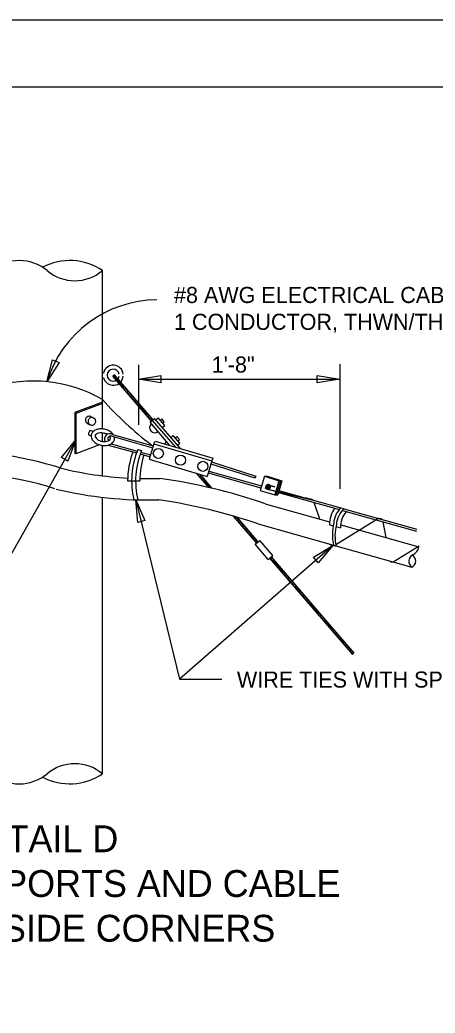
# Model space of a CAD drawing. Extents: x 1299104.8 to 1299141.6, y 239639.8 to 239661.8.
# Drawn here: x 1299131.21 to 1299134.3, y 239654.39 to 239661.79 of the extents above; entities that cross this region are included whole.
import ezdxf

# ---------------------------------------------------------------- set-up
doc = ezdxf.new("R2010")
doc.units = 0
for name, color, linetype in [('DIM TXT', 7, 'Continuous'), ('GS_plotshape_p', 7, 'Continuous'), ('Level 1', 7, 'Continuous')]:
    doc.layers.add(name, color=color, linetype=linetype)

msp = doc.modelspace()

# ---------------------------------------------------------------- linework, layer by layer
at = {"layer": 'DIM TXT'}
for p, q in [((1299131.8243, 239658.7425), (1299131.8243, 239659.9223)), ((1299132.0934, 239659.2193), (1299132.0934, 239658.7737)), ((1299133.5917, 239659.2257), (1299133.5917, 239658.2954)), ((1299131.8243, 239659.1615), (1299131.8325, 239659.1615)), ((1299131.8243, 239659.124), (1299131.8325, 239659.124)), ((1299131.9132, 239659.1462), (1299131.9018, 239659.1364)), ((1299132.1903, 239658.8014), (1299131.9018, 239659.1364)), ((1299131.9132, 239659.1462), (1299131.9116, 239659.125)), ((1299132.2017, 239658.8112), (1299131.9132, 239659.1462)), ((1299131.923, 239659.1348), (1299131.9214, 239659.1136)), ((1299131.9328, 239659.1234), (1299131.9312, 239659.1023)), ((1299131.9425, 239659.1121), (1299131.941, 239659.0909)), ((1299131.9523, 239659.1007), (1299131.9508, 239659.0795)), ((1299131.9621, 239659.0893), (1299131.9605, 239659.0682)), ((1299131.9719, 239659.078), (1299131.9703, 239659.0568)), ((1299131.9817, 239659.0666), (1299131.9801, 239659.0455)), ((1299131.9915, 239659.0552), (1299131.9899, 239659.0341)), ((1299132.0013, 239659.0439), (1299131.9997, 239659.0227)), ((1299132.0934, 239659.1124), (1299133.5917, 239659.1124)), ((1299132.0111, 239659.0325), (1299132.0095, 239659.0114)), ((1299132.0209, 239659.0211), (1299132.0193, 239659)), ((1299132.0307, 239659.0098), (1299132.0291, 239658.9886)), ((1299132.0404, 239658.9984), (1299132.0389, 239658.9773)), ((1299132.0502, 239658.9871), (1299132.0487, 239658.9659)), ((1299132.06, 239658.9757), (1299132.0584, 239658.9545)), ((1299131.8243, 239658.9424), (1299131.6185, 239658.865)), ((1299131.8243, 239658.9331), (1299131.6262, 239658.8586)), ((1299132.0698, 239658.9643), (1299132.0682, 239658.9432)), ((1299132.0796, 239658.953), (1299132.078, 239658.9318)), ((1299132.0894, 239658.9416), (1299132.0878, 239658.9204)), ((1299132.0992, 239658.9302), (1299132.0976, 239658.9091)), ((1299132.109, 239658.9189), (1299132.1074, 239658.8977)), ((1299132.1188, 239658.9075), (1299132.1172, 239658.8863)), ((1299132.1285, 239658.8961), (1299132.127, 239658.875)), ((1299131.6185, 239658.865), (1299131.6185, 239658.5624)), ((1299131.6185, 239658.865), (1299131.6262, 239658.8586)), ((1299131.6262, 239658.8586), (1299131.6262, 239658.5575)), ((1299131.7368, 239658.8352), (1299131.761, 239658.8235)), ((1299132.1383, 239658.8848), (1299132.1368, 239658.8636)), ((1299132.1481, 239658.8734), (1299132.1465, 239658.8522)), ((1299132.1579, 239658.862), (1299132.1563, 239658.8409)), ((1299132.1677, 239658.8507), (1299132.1661, 239658.8295)), ((1299132.1786, 239658.8381), (1299132.177, 239658.8169)), ((1299132.1789, 239658.7917), (1299132.213, 239658.821)), ((1299132.1894, 239658.8254), (1299132.1879, 239658.8043)), ((1299132.4067, 239658.5962), (1299132.213, 239658.821)), ((1299132.2228, 239658.8097), (1299132.2399, 239658.8243)), ((1299132.2888, 239658.7675), (1299132.2399, 239658.8243)), ((1299131.7169, 239658.7813), (1299131.7341, 239658.7728)), ((1299132.3271, 239658.6196), (1299132.1789, 239658.7917)), ((1299132.196, 239658.8063), (1299132.3669, 239658.6079)), ((1299132.2546, 239658.8073), (1299132.2659, 239658.8171)), ((1299132.2855, 239658.7944), (1299132.2659, 239658.8171)), ((1299132.2718, 239658.7528), (1299132.2888, 239658.7675)), ((1299132.2741, 239658.7846), (1299132.2855, 239658.7944)), ((1299131.7196, 239658.6975), (1299131.7401, 239658.6901)), ((1299131.7332, 239658.7325), (1299131.7568, 239658.7239)), ((1299131.8243, 239658.6496), (1299131.8243, 239658.7124)), ((1299131.8863, 239658.6901), (1299132.1991, 239658.6028)), ((1299131.8992, 239658.7021), (1299132.2033, 239658.6172)), ((1299132.3354, 239658.679), (1299132.3525, 239658.6936)), ((1299132.4014, 239658.6368), (1299132.3525, 239658.6936)), ((1299132.3671, 239658.6766), (1299132.3785, 239658.6864)), ((1299132.3981, 239658.6637), (1299132.3785, 239658.6864)), ((1299131.6262, 239658.662), (1299130.2172, 239656.1718)), ((1299131.8028, 239658.6239), (1299131.6262, 239658.5575)), ((1299131.8243, 239658.3931), (1299131.8243, 239658.6193)), ((1299131.8672, 239658.6222), (1299132.0786, 239658.5632)), ((1299131.8899, 239658.6315), (1299132.084, 239658.5773)), ((1299132.2074, 239658.631), (1299132.1735, 239658.5159)), ((1299132.2074, 239658.631), (1299132.2176, 239658.6519)), ((1299132.2074, 239658.631), (1299132.6391, 239658.5039)), ((1299132.2176, 239658.6519), (1299132.6493, 239658.5248)), ((1299132.3844, 239658.6221), (1299132.4014, 239658.6368)), ((1299132.3867, 239658.6539), (1299132.3981, 239658.6637)), ((1299131.6262, 239658.5575), (1299131.6185, 239658.5624)), ((1299132.0886, 239658.5885), (1299132.1153, 239658.5813)), ((1299132.1056, 239658.5556), (1299132.1792, 239658.5351)), ((1299132.1108, 239658.5698), (1299132.1834, 239658.5495)), ((1299132.6391, 239658.5039), (1299132.6493, 239658.5248)), ((1299132.1735, 239658.5159), (1299132.6052, 239658.3888)), ((1299132.6391, 239658.5039), (1299132.6052, 239658.3888)), ((1299132.6318, 239658.4818), (1299132.9593, 239658.3768)), ((1299132.6366, 239658.496), (1299132.9658, 239658.3904)), ((1299132.6175, 239658.3055), (1299132.5256, 239658.4122)), ((1299132.5334, 239658.4099), (1299132.5329, 239658.4037)), ((1299132.5438, 239658.4069), (1299132.5427, 239658.3923)), ((1299132.6423, 239658.2996), (1299132.5521, 239658.4044)), ((1299132.5541, 239658.4021), (1299132.5525, 239658.3809)), ((1299132.5639, 239658.3907), (1299132.5623, 239658.3696)), ((1299132.5737, 239658.3794), (1299132.5721, 239658.3582)), ((1299132.6126, 239658.4141), (1299133.005, 239658.3045)), ((1299132.6169, 239658.4284), (1299133.0092, 239658.3189)), ((1299132.9658, 239658.3904), (1299132.9593, 239658.3768)), ((1299133.0305, 239658.3913), (1299132.9989, 239658.2839)), ((1299133.0305, 239658.3913), (1299133.1384, 239658.3567)), ((1299133.0305, 239658.3913), (1299133.0529, 239658.3909)), ((1299133.0425, 239658.3911), (1299133.1504, 239658.3565)), ((1299133.0529, 239658.3909), (1299133.1608, 239658.3563)), ((1299132.0123, 239658.3564), (1299132.1024, 239658.3564)), ((1299132.5835, 239658.368), (1299132.5819, 239658.3468)), ((1299132.5933, 239658.3566), (1299132.5917, 239658.3355)), ((1299132.603, 239658.3453), (1299132.6015, 239658.3241)), ((1299132.6128, 239658.3339), (1299132.6113, 239658.3127)), ((1299132.6226, 239658.3225), (1299132.6213, 239658.3046)), ((1299132.6324, 239658.3112), (1299132.6317, 239658.3022)), ((1299133.0539, 239658.3102), (1299133.0413, 239658.3055)), ((1299133.0542, 239658.3022), (1299133.0445, 239658.2982)), ((1299133.0502, 239658.3153), (1299133.0533, 239658.317)), ((1299133.0595, 239658.3139), (1299133.0627, 239658.3156)), ((1299133.063, 239658.3051), (1299133.0662, 239658.3067)), ((1299133.0685, 239658.3229), (1299133.1055, 239658.314)), ((1299133.0708, 239658.3204), (1299133.1053, 239658.3121)), ((1299133.1384, 239658.3567), (1299133.1078, 239658.2525)), ((1299133.1504, 239658.3565), (1299133.1194, 239658.2511)), ((1299133.1608, 239658.3563), (1299133.1301, 239658.2521)), ((1299133.1384, 239658.3567), (1299133.1608, 239658.3563)), ((1299131.8243, 239656.1723), (1299131.8243, 239658.2326)), ((1299132.9989, 239658.2839), (1299133.1078, 239658.2525)), ((1299133.0525, 239658.2937), (1299133.3853, 239658.2139)), ((1299133.0571, 239658.2977), (1299133.0603, 239658.2993)), ((1299133.0572, 239658.2945), (1299133.3363, 239658.2275)), ((1299133.1078, 239658.2525), (1299133.1301, 239658.2521)), ((1299133.1252, 239658.2709), (1299133.5892, 239658.1413)), ((1299133.1294, 239658.2853), (1299133.6011, 239658.1536)), ((1299132.0735, 239658.2142), (1299132.3981, 239656.8768)), ((1299133.0362, 239658.185), (1299133.5163, 239658.0502)), ((1299133.3946, 239658.2112), (1299133.3944, 239658.2118)), ((1299133.443, 239658.0707), (1299133.4006, 239658.194)), ((1299133.6027, 239658.1551), (1299133.6248, 239658.1484)), ((1299132.9735, 239657.8922), (1299132.8008, 239658.0927)), ((1299132.8178, 239658.0876), (1299132.8168, 239658.0741)), ((1299132.8282, 239658.0839), (1299132.8266, 239658.0627)), ((1299132.9848, 239657.902), (1299132.8274, 239658.0848)), ((1299133.6113, 239658.1352), (1299134.1641, 239657.9808)), ((1299133.6236, 239658.1473), (1299134.1668, 239657.9956)), ((1299132.838, 239658.0725), (1299132.8364, 239658.0513)), ((1299132.8478, 239658.0611), (1299132.8462, 239658.04)), ((1299132.8576, 239658.0498), (1299132.856, 239658.0286)), ((1299132.8674, 239658.0384), (1299132.8658, 239658.0173)), ((1299132.8771, 239658.027), (1299132.8756, 239658.0059)), ((1299132.8869, 239658.0157), (1299132.8854, 239657.9945)), ((1299132.9842, 239658.0343), (1299133.5457, 239657.8766)), ((1299133.5162, 239658.0287), (1299133.5429, 239658.0213)), ((1299133.5623, 239657.8802), (1299133.8817, 239658.0772)), ((1299133.5635, 239658.0155), (1299133.5985, 239658.0057)), ((1299133.5989, 239658.027), (1299134.1801, 239657.8638)), ((1299133.8817, 239658.0772), (1299133.8988, 239658.0743)), ((1299133.8988, 239658.0743), (1299133.9089, 239658.0686)), ((1299133.9089, 239658.0686), (1299133.9091, 239658.0676)), ((1299133.9122, 239658.0511), (1299133.9345, 239657.9328)), ((1299132.8967, 239658.0043), (1299132.8952, 239657.9832)), ((1299132.9065, 239657.9929), (1299132.9049, 239657.9718)), ((1299132.9163, 239657.9816), (1299132.9147, 239657.9604)), ((1299132.9261, 239657.9702), (1299132.9245, 239657.9491)), ((1299132.9359, 239657.9589), (1299132.9343, 239657.9377)), ((1299132.9457, 239657.9475), (1299132.9441, 239657.9263)), ((1299132.9555, 239657.9361), (1299132.9539, 239657.915)), ((1299133.5403, 239657.8742), (1299132.3981, 239656.8768)), ((1299132.9621, 239657.8824), (1299132.9962, 239657.9118)), ((1299133.06, 239657.7688), (1299132.9621, 239657.8824)), ((1299132.9653, 239657.9248), (1299132.9637, 239657.9036)), ((1299132.975, 239657.9134), (1299132.9735, 239657.8922)), ((1299133.0941, 239657.7982), (1299132.9962, 239657.9118)), ((1299133.5059, 239657.8878), (1299133.5326, 239657.8748)), ((1299133.5326, 239657.8748), (1299133.5512, 239657.8734)), ((1299133.5461, 239657.8749), (1299133.5645, 239657.869)), ((1299133.564, 239657.8715), (1299134.1281, 239657.7131)), ((1299133.99, 239657.7508), (1299134.1826, 239657.8706)), ((1299133.06, 239657.7688), (1299133.0941, 239657.7982)), ((1299133.0827, 239657.7884), (1299133.0812, 239657.7672)), ((1299133.6998, 239657.072), (1299133.0827, 239657.7884)), ((1299133.6894, 239657.0611), (1299133.0714, 239657.7786)), ((1299133.0925, 239657.777), (1299133.0909, 239657.7559)), ((1299133.1023, 239657.7656), (1299133.1007, 239657.7445)), ((1299133.1121, 239657.7543), (1299133.1105, 239657.7331)), ((1299133.1219, 239657.7429), (1299133.1203, 239657.7218)), ((1299133.1317, 239657.7316), (1299133.1301, 239657.7104)), ((1299133.1415, 239657.7202), (1299133.1399, 239657.699)), ((1299133.9673, 239657.7583), (1299133.9674, 239657.758)), ((1299133.9674, 239657.758), (1299133.9757, 239657.7523)), ((1299133.9757, 239657.7523), (1299133.99, 239657.7508)), ((1299133.1513, 239657.7088), (1299133.1497, 239657.6877)), ((1299133.161, 239657.6975), (1299133.1595, 239657.6763)), ((1299133.1708, 239657.6861), (1299133.1693, 239657.6649)), ((1299133.1806, 239657.6747), (1299133.179, 239657.6536)), ((1299133.1904, 239657.6634), (1299133.1888, 239657.6422)), ((1299133.2002, 239657.652), (1299133.1986, 239657.6308)), ((1299133.21, 239657.6406), (1299133.2084, 239657.6195)), ((1299133.2198, 239657.6293), (1299133.2182, 239657.6081)), ((1299133.2296, 239657.6179), (1299133.228, 239657.5967)), ((1299133.2394, 239657.6065), (1299133.2378, 239657.5854)), ((1299133.2492, 239657.5952), (1299133.2476, 239657.574)), ((1299133.2632, 239657.5792), (1299133.2617, 239657.558)), ((1299133.273, 239657.5678), (1299133.2715, 239657.5467)), ((1299133.2828, 239657.5565), (1299133.2812, 239657.5353)), ((1299133.2926, 239657.5451), (1299133.291, 239657.5239)), ((1299133.3024, 239657.5337), (1299133.3008, 239657.5126)), ((1299133.3122, 239657.5224), (1299133.3106, 239657.5012)), ((1299133.322, 239657.511), (1299133.3204, 239657.4898)), ((1299133.3318, 239657.4996), (1299133.3302, 239657.4785)), ((1299133.3416, 239657.4883), (1299133.34, 239657.4671)), ((1299133.3513, 239657.4769), (1299133.3498, 239657.4557)), ((1299133.3611, 239657.4655), (1299133.3596, 239657.4444)), ((1299133.3709, 239657.4542), (1299133.3693, 239657.433)), ((1299133.3803, 239657.4429), (1299133.3787, 239657.4218)), ((1299133.3901, 239657.4316), (1299133.3885, 239657.4104)), ((1299133.3999, 239657.4202), (1299133.3983, 239657.3991)), ((1299133.4096, 239657.4088), (1299133.4081, 239657.3877)), ((1299133.4194, 239657.3975), (1299133.4179, 239657.3763)), ((1299133.4292, 239657.3861), (1299133.4276, 239657.365)), ((1299133.439, 239657.3748), (1299133.4374, 239657.3536)), ((1299133.4488, 239657.3634), (1299133.4472, 239657.3422)), ((1299133.4586, 239657.352), (1299133.457, 239657.3309)), ((1299133.4684, 239657.3407), (1299133.4668, 239657.3195)), ((1299133.4782, 239657.3293), (1299133.4766, 239657.3081)), ((1299133.488, 239657.3179), (1299133.4864, 239657.2968)), ((1299133.4967, 239657.3053), (1299133.4951, 239657.2841)), ((1299133.5064, 239657.2939), (1299133.5049, 239657.2728)), ((1299133.5162, 239657.2825), (1299133.5147, 239657.2614)), ((1299133.526, 239657.2712), (1299133.5245, 239657.25)), ((1299133.5358, 239657.2598), (1299133.5342, 239657.2387)), ((1299133.5456, 239657.2485), (1299133.544, 239657.2273)), ((1299133.5554, 239657.2371), (1299133.5538, 239657.2159)), ((1299133.5652, 239657.2257), (1299133.5636, 239657.2046)), ((1299133.575, 239657.2144), (1299133.5734, 239657.1932)), ((1299133.5848, 239657.203), (1299133.5832, 239657.1818)), ((1299133.5946, 239657.1916), (1299133.593, 239657.1705)), ((1299133.6032, 239657.1819), (1299133.6017, 239657.1607)), ((1299133.6131, 239657.1723), (1299133.6116, 239657.1512)), ((1299133.6225, 239657.1622), (1299133.6209, 239657.1411)), ((1299133.6323, 239657.1508), (1299133.6307, 239657.1297)), ((1299133.6421, 239657.1395), (1299133.6405, 239657.1183)), ((1299133.6519, 239657.1281), (1299133.6503, 239657.107)), ((1299133.6617, 239657.1168), (1299133.6601, 239657.0956)), ((1299133.6715, 239657.1054), (1299133.6699, 239657.0842)), ((1299133.6812, 239657.094), (1299133.6797, 239657.0729)), ((1299133.691, 239657.0827), (1299133.6895, 239657.0615)), ((1299132.3981, 239656.8768), (1299132.7138, 239656.8768))]:
    msp.add_line(p, q, dxfattribs=at)
for points in [[(1299131.4519, 239659.2579), (1299131.5018, 239659.2364), (1299131.411, 239659.0939)], [(1299132.2603, 239659.1396), (1299132.2603, 239659.0852), (1299132.0934, 239659.1124)], [(1299133.4248, 239659.0852), (1299133.4248, 239659.1396), (1299133.5917, 239659.1124)], [(1299131.5677, 239658.5034), (1299131.5204, 239658.5302), (1299131.6262, 239658.662)], [(1299132.141, 239658.0592), (1299132.0884, 239658.0458), (1299132.0735, 239658.2142)], [(1299133.4313, 239657.745), (1299133.3959, 239657.7863), (1299133.5403, 239657.8742)]]:
    msp.add_lwpolyline(points, close=True, dxfattribs=at)
for points in [[(1299133.0502, 239658.3153), (1299133.0443, 239658.3079), (1299133.0447, 239658.3068)], [(1299133.0476, 239658.2995), (1299133.0477, 239658.2991), (1299133.0571, 239658.2977), (1299133.063, 239658.3051)], [(1299133.063, 239658.3051), (1299133.0595, 239658.3139), (1299133.0502, 239658.3153)], [(1299133.0662, 239658.3067), (1299133.0627, 239658.3156), (1299133.0533, 239658.317)], [(1299133.0603, 239658.2993), (1299133.0662, 239658.3067)]]:
    msp.add_lwpolyline(points, dxfattribs=at)
for centre, radius in [((1299132.2407, 239658.5601), 0.0375), ((1299132.4063, 239658.51), 0.0375), ((1299132.5732, 239658.4636), 0.0375), ((1299133.042, 239658.3015), 0.00408)]:
    msp.add_circle(centre, radius, dxfattribs=at)
for centre, radius, start, end in [((1299131.2055, 239659.6762), 0.3211, 50.03379, 129.96621), ((1299131.5805, 239659.5637), 0.4336, 55.79454, 117.85169), ((1299131.618, 239660.1684), 0.3211, 230.03379, 309.96621), ((1299132.239, 239658.8385), 0.8666, 90.62427, 162.85937), ((1299131.9051, 239659.1428), 0.075, 5.73917, 165.52249), ((1299131.9051, 239659.1428), 0.075, 194.47751, 354.26083), ((1299131.9051, 239659.1428), 0.045, 9.59407, 350.40593), ((1299131.3088, 239658.0608), 1.0381, 60.22849, 107.47221), ((1299133.7639, 239660.6889), 2.5971, 221.68102, 232.67437), ((1299131.7267, 239658.8083), 0.0289, 149.78698, 172.19682), ((1299131.7267, 239658.8083), 0.0289, 127.37714, 149.78698), ((1299131.7267, 239658.8084), 0.0287, 104.91468, 127.37714), ((1299131.7266, 239658.8085), 0.0286, 82.37742, 104.91468), ((1299131.7461, 239658.7989), 0.0289, 127.37714, 149.78698), ((1299131.746, 239658.799), 0.0287, 104.91468, 127.37714), ((1299131.7266, 239658.8086), 0.0285, 69.046, 82.37742), ((1299131.746, 239658.7991), 0.0286, 82.37742, 104.91468), ((1299131.746, 239658.7992), 0.0285, 59.78698, 82.37742), ((1299131.746, 239658.7992), 0.0285, 37.19653, 59.78698), ((1299131.7266, 239658.8083), 0.0287, 172.19682, 194.65927), ((1299131.7265, 239658.8082), 0.0286, 194.65927, 217.19653), ((1299131.7264, 239658.8082), 0.0285, 217.19653, 239.78698), ((1299131.7264, 239658.8082), 0.0285, 239.78698, 250.59071), ((1299131.746, 239658.7989), 0.0287, 172.19682, 194.65927), ((1299131.7461, 239658.7989), 0.0289, 149.78698, 172.19682), ((1299131.7459, 239658.7989), 0.0286, 194.65927, 217.19653), ((1299131.7458, 239658.7988), 0.0285, 217.19653, 239.78698), ((1299131.7458, 239658.7988), 0.0285, 239.78698, 262.37742), ((1299131.7458, 239658.7989), 0.0286, 262.37742, 284.91468), ((1299131.7458, 239658.799), 0.0287, 284.91468, 307.37714), ((1299131.7457, 239658.7991), 0.0289, 307.37714, 329.78698), ((1299131.7459, 239658.7992), 0.0286, 14.65927, 37.19653), ((1299131.7457, 239658.7991), 0.0289, 329.78698, 352.19682), ((1299131.7458, 239658.7991), 0.0287, 352.19682, 14.65927), ((1299132.2132, 239658.7519), 0.0375, 130.74057, 310.74057), ((1299131.7728, 239658.697), 0.0532, 167.42818, 179.43021), ((1299131.7728, 239658.697), 0.0532, 138.67908, 167.42818), ((1299131.7889, 239658.6828), 0.0746, 138.29739, 138.67908), ((1299131.7831, 239658.6895), 0.0431, 168.52616, 199.38211), ((1299131.7831, 239658.6895), 0.0431, 137.67021, 168.52616), ((1299131.8068, 239658.6979), 0.0682, 199.38211, 223.79222), ((1299131.8017, 239658.6726), 0.0682, 113.2601, 137.67021), ((1299131.7831, 239658.6895), 0.0131, 168.52616, 199.38211), ((1299131.7831, 239658.6895), 0.0131, 137.67021, 168.52616), ((1299131.8068, 239658.6979), 0.0382, 199.38211, 223.79222), ((1299131.8017, 239658.6726), 0.0382, 113.2601, 137.67021), ((1299131.8115, 239658.6498), 0.093, 94.54907, 113.2601), ((1299131.8115, 239658.6498), 0.063, 94.54907, 113.2601), ((1299131.8142, 239658.6164), 0.1265, 78.52616, 94.54907), ((1299131.8142, 239658.6164), 0.0965, 78.52616, 94.54907), ((1299131.8142, 239658.6164), 0.0965, 62.50325, 78.52616), ((1299131.8142, 239658.6164), 0.1265, 62.50325, 78.52616), ((1299131.88, 239658.6661), 0.0408, 61.92341, 205.91256), ((1299131.8296, 239658.6461), 0.063, 61.46787, 62.50325), ((1299131.8854, 239658.6696), 0.0206, 61.46209, 225.1877), ((1299131.8296, 239658.6461), 0.093, 43.79222, 62.50325), ((1299131.8476, 239658.6633), 0.0382, 19.38211, 40.60323), ((1299131.8713, 239658.6716), 0.0131, 348.52616, 19.38211), ((1299131.8476, 239658.6633), 0.0682, 33.14833, 43.79222), ((1299131.8713, 239658.6716), 0.0431, 348.52616, 14.90203), ((1299131.8248, 239658.715), 0.093, 223.79222, 242.50325), ((1299131.8248, 239658.715), 0.063, 223.79222, 242.50325), ((1299131.8402, 239658.7448), 0.1265, 242.50325, 258.52616), ((1299131.8402, 239658.7448), 0.0965, 242.50325, 258.52616), ((1299131.8402, 239658.7448), 0.1265, 258.52616, 274.54907), ((1299131.8402, 239658.7448), 0.0965, 258.52616, 274.54907), ((1299131.8429, 239658.7113), 0.063, 274.54907, 293.2601), ((1299131.8429, 239658.7113), 0.093, 274.54907, 293.2601), ((1299131.8527, 239658.6886), 0.0382, 293.2601, 317.67021), ((1299131.8527, 239658.6886), 0.0682, 293.2601, 317.67021), ((1299131.8713, 239658.6716), 0.0131, 317.67021, 348.52616), ((1299131.8713, 239658.6716), 0.0431, 317.67021, 348.52616), ((1299132.3258, 239658.6212), 0.0375, 130.74057, 165.28012), ((1299130.7213, 239655.96), 2.6133, 72.24591, 93.70981), ((1299132.6141, 239658.3564), 0.6018, 159.40629, 180), ((1299132.6438, 239658.3564), 0.6018, 157.30675, 193.6218), ((1299132.6734, 239658.3564), 0.6018, 158.04982, 193.71187), ((1299132.7042, 239658.3564), 0.6018, 161.45038, 180), ((1299130.7213, 239655.96), 2.4539, 72.24591, 95.77175), ((1299132.1634, 239661.1268), 2.7546, 256.45152, 266.86214), ((1299132.1634, 239661.1268), 2.7546, 268.73537, 271.85609), ((1299131.6622, 239654.2), 4.2152, 70.97653, 81.9475), ((1299133.057, 239658.3101), 0.0172, 223.69363, 196.41961), ((1299133.043, 239658.3018), 0.00408, 309.40767, 102.03168), ((1299133.044, 239658.3022), 0.00408, 311.84408, 117.1852), ((1299133.0452, 239658.3027), 0.00408, 309.40767, 96.9335), ((1299133.0463, 239658.3031), 0.00408, 311.84408, 98.37244), ((1299133.0474, 239658.3036), 0.00408, 311.84408, 96.13701), ((1299133.0486, 239658.3041), 0.00408, 309.40767, 91.60657), ((1299133.0497, 239658.3045), 0.00408, 311.84408, 92.62242), ((1299133.0597, 239658.3115), 0.0172, 36.4414, 122.35212), ((1299133.0508, 239658.3049), 0.00408, 311.84408, 91.16995), ((1299133.052, 239658.3055), 0.00408, 309.40767, 87.571), ((1299133.053, 239658.3058), 0.00408, 322.72939, 88.40842), ((1299133.0533, 239658.3062), 0.00408, 283.85937, 81.73019), ((1299133.0597, 239658.3115), 0.0172, 292.43109, 27.51642), ((1299132.1634, 239661.1268), 2.914, 256.45152, 271.57798), ((1299131.6622, 239654.2), 4.0558, 70.97653, 81.75694), ((1299131.2816, 239648.3998), 10.0402, 77.98839, 78.19132), ((1299133.353, 239658.1351), 0.087, 61.16103, 77.98839), ((1299133.7181, 239658.0283), 0.1714, 132.30194, 176.40305), ((1299133.6874, 239658.0394), 0.1714, 139.65334, 183.57085), ((1299133.7379, 239658.0195), 0.1714, 131.27831, 176.40305), ((1299133.7698, 239658.0132), 0.1714, 139.65334, 182.5094), ((1299133.9002, 239657.9559), 0.3633, 166.37774, 192.8823), ((1299133.9198, 239657.9447), 0.3633, 166.37774, 192.02563), ((1299134.101, 239657.875), 0.0798, 296.07792, 351.91055), ((1299134.1594, 239657.7558), 0.0529, 116.07792, 233.77556), ((1299134.109, 239657.758), 0.0487, 293.02688, 62.03838), ((1299131.618, 239655.9262), 0.3211, 50.03379, 129.96621), ((1299131.2055, 239656.4184), 0.3211, 230.03379, 309.96621), ((1299131.5805, 239656.5309), 0.4336, 242.14831, 304.20546)]:
    msp.add_arc(centre, radius, start, end, dxfattribs=at)
at = {"layer": 'GS_plotshape_p'}
msp.add_lwpolyline([(1299104.8019, 239661.7913), (1299138.8019, 239661.7913), (1299138.8019, 239639.7913), (1299104.8019, 239639.7913)], close=True, dxfattribs=at)
at = {"layer": 'Level 1'}
msp.add_lwpolyline([(1299138.3019, 239640.2913), (1299106.3019, 239640.2913), (1299106.3019, 239661.2913), (1299138.3019, 239661.2913)], close=True, dxfattribs=at)

# ---------------------------------------------------------------- texts
at = {"layer": 'DIM TXT'}
for s, height, p in [('#8 AWG ELECTRICAL CABLE, COPPER, ', 0.12, (1299132.3574, 239659.681)), ('1 CONDUCTOR, THWN/THHN INSULATED', 0.12, (1299132.3574, 239659.481)), ('1\'-8"', 0.12, (1299132.6383, 239659.1624)), ('WIRE TIES WITH SPACERS', 0.12, (1299132.826, 239656.8144)), ('DETAIL D', 0.2, (1299130.739, 239655.5877)), ('LASHED CABLE SUPPORTS AND CABLE ', 0.2, (1299128.4398, 239655.2543)), ('SPACERS AT INSIDE CORNERS', 0.2, (1299129.0398, 239654.921))]:
    msp.add_text(s, height=height, dxfattribs=at).set_placement(p)

doc.saveas('drawing.dxf')
